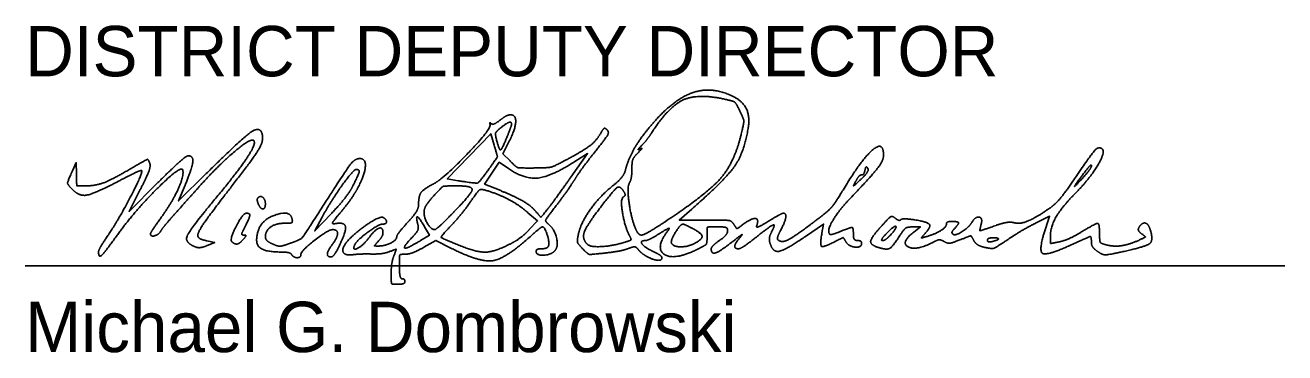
# Model space of a CAD drawing. Extents: x -6.4 to 34, y -1.2 to 22.
# Drawn here: x 25.5 to 29, y 3.231 to 4.142 of the extents above; entities that cross this region are included whole.
import ezdxf

# ---------------------------------------------------------------- set-up
doc = ezdxf.new("R2010")
doc.units = 0
doc.layers.add('GM_X_Airport_Location_Class_3', color=7, linetype='Continuous')
doc.layers.add('GM_X_Township', color=7, linetype='Continuous')

msp = doc.modelspace()

# ---------------------------------------------------------------- linework, layer by layer
at = {"layer": 'GM_X_Airport_Location_Class_3'}
for p, q in [((27.8411, 3.7444), (27.8411, 3.7444)), ((26.1473, 3.6463), (26.1473, 3.6463)), ((26.074, 3.5405), (26.074, 3.5405)), ((25.7038, 3.5122), (25.7038, 3.5122))]:
    msp.add_line(p, q, dxfattribs=at)
for points in [[(26.7032, 3.7097), (26.6728, 3.7146), (26.7937, 3.8403), (26.8032, 3.8082)], [(26.8471, 3.7647), (26.8273, 3.7845), (26.8431, 3.8157)], [(27.0277, 3.7631), (27.0627, 3.7853), (27.016, 3.7193)], [(25.6314, 3.7372), (25.6418, 3.76), (25.6424, 3.7277)], [(26.8166, 3.684), (26.7763, 3.7003), (26.7968, 3.7307), (26.8172, 3.7611), (26.8431, 3.7434)], [(25.9443, 3.6972), (25.9263, 3.6536), (26.0032, 3.7296)], [(25.8197, 3.6852), (25.7885, 3.6245), (25.866, 3.7018)], [(26.3498, 3.6176), (26.3044, 3.57), (26.3252, 3.6087)], [(26.897, 3.6209), (26.9236, 3.598), (26.9008, 3.5738)], [(27.3894, 3.6004), (27.3173, 3.6004), (27.352, 3.6308)], [(28.3075, 3.5916), (28.3462, 3.6108), (28.3348, 3.5761)], [(26.6099, 3.5811), (26.623, 3.5581), (26.5985, 3.5432)], [(27.6683, 3.555), (27.7186, 3.5894), (27.7137, 3.5635)], [(27.9668, 3.5812), (27.9876, 3.5811), (27.9693, 3.567)], [(26.0047, 3.5427), (26.0268, 3.5382), (26.006, 3.5296)], [(26.6073, 3.5246), (26.6406, 3.5436), (26.6864, 3.5207)]]:
    msp.add_lwpolyline(points, dxfattribs=at)
for points in [[(27.467, 3.9441), (27.4102, 3.9725), (27.3049, 3.9384), (27.2472, 3.8728)], [(27.239, 3.8404), (27.2861, 3.914), (27.3666, 3.9528), (27.44, 3.9372)], [(27.44, 3.9372), (27.4676, 3.9313), (27.4755, 3.9254), (27.486, 3.9034)], [(27.5088, 3.855), (27.5142, 3.8878), (27.4942, 3.9305), (27.467, 3.9441)], [(26.8487, 3.893), (26.843, 3.893), (26.8297, 3.8863), (26.8193, 3.8781)], [(26.8431, 3.8157), (26.8614, 3.8515), (26.8644, 3.893), (26.8487, 3.893)], [(27.486, 3.9034), (27.4968, 3.8806), (27.4973, 3.8711), (27.4897, 3.8393)], [(26.0032, 3.7296), (26.0977, 3.8229), (26.1501, 3.8618), (26.157, 3.8437)], [(26.7919, 3.8658), (26.7955, 3.854), (26.6624, 3.7152), (26.6332, 3.7002)], [(26.7948, 3.8686), (26.7918, 3.8716), (26.7905, 3.8703), (26.7919, 3.8658)], [(26.8193, 3.8781), (26.8088, 3.8698), (26.7978, 3.8656), (26.7948, 3.8686)], [(26.8099, 3.8225), (26.8058, 3.8386), (26.8084, 3.8463), (26.8213, 3.8567)], [(26.8213, 3.8567), (26.8372, 3.8696), (26.8514, 3.8743), (26.8514, 3.8666)], [(26.8514, 3.8666), (26.8514, 3.8646), (26.8459, 3.8492), (26.8392, 3.8324)], [(27.0861, 3.7938), (27.114, 3.8286), (27.1229, 3.8449), (27.1171, 3.8507)], [(27.1171, 3.8507), (27.1113, 3.8565), (27.1067, 3.8549), (27.1013, 3.8454)], [(27.2472, 3.8728), (27.2136, 3.8347), (27.1756, 3.7709), (27.168, 3.7398)], [(27.352, 3.6308), (27.4443, 3.7115), (27.4977, 3.7879), (27.5088, 3.855)], [(26.135, 3.8215), (26.1273, 3.8293), (26.0363, 3.7523), (25.9838, 3.6935)], [(26.0419, 3.6764), (26.0961, 3.7418), (26.1425, 3.8141), (26.135, 3.8215)], [(26.157, 3.8437), (26.164, 3.8257), (26.1419, 3.7824), (26.0952, 3.722)], [(26.8392, 3.8324), (26.8249, 3.7966), (26.8171, 3.7939), (26.8099, 3.8225)], [(27.1013, 3.8454), (27.0882, 3.8222), (27.055, 3.7955), (27.0075, 3.77)], [(27.2124, 3.8073), (27.2208, 3.8157), (27.2328, 3.8306), (27.239, 3.8404)], [(27.4897, 3.8393), (27.4708, 3.7606), (27.3943, 3.6726), (27.278, 3.5957)], [(26.8032, 3.8082), (26.8124, 3.7772), (26.8118, 3.7748), (26.7879, 3.7414)], [(27.0278, 3.7145), (27.0383, 3.7313), (27.0646, 3.767), (27.0861, 3.7938)], [(27.1857, 3.7426), (27.1858, 3.7618), (27.1913, 3.7761), (27.2029, 3.7874)], [(27.2029, 3.7874), (27.2123, 3.7966), (27.2149, 3.8013), (27.2086, 3.798)], [(27.2086, 3.798), (27.2024, 3.7947), (27.2041, 3.7989), (27.2124, 3.8073)], [(27.885, 3.7804), (27.885, 3.8217), (27.8234, 3.7686), (27.7724, 3.6835)], [(27.7929, 3.6612), (27.8522, 3.7232), (27.885, 3.7656), (27.885, 3.7804)], [(28.4913, 3.7991), (28.4817, 3.805), (28.4617, 3.7823), (28.4091, 3.7056)], [(28.4203, 3.6773), (28.4591, 3.7165), (28.503, 3.7918), (28.4913, 3.7991)], [(25.6687, 3.6954), (25.6965, 3.6954), (25.7456, 3.715), (25.804, 3.7494)], [(25.804, 3.7494), (25.8369, 3.7688), (25.8417, 3.7699), (25.846, 3.7586)], [(25.846, 3.7586), (25.849, 3.7509), (25.8386, 3.7219), (25.8197, 3.6852)], [(25.866, 3.7018), (25.9086, 3.7442), (25.9477, 3.779), (25.9529, 3.779)], [(25.9529, 3.779), (25.9675, 3.779), (25.9639, 3.7448), (25.9443, 3.6972)], [(26.43, 3.7714), (26.416, 3.7714), (26.3902, 3.7378), (26.3225, 3.6317)], [(26.4251, 3.6915), (26.4438, 3.7271), (26.4466, 3.7714), (26.43, 3.7714)], [(26.8431, 3.7434), (26.8873, 3.7132), (26.9615, 3.7211), (27.0277, 3.7631)], [(26.9143, 3.7451), (26.8733, 3.7448), (26.8644, 3.7474), (26.8471, 3.7647)], [(27.0075, 3.77), (26.9701, 3.7499), (26.9529, 3.7453), (26.9143, 3.7451)], [(27.8411, 3.7444), (27.8381, 3.7491), (27.8349, 3.747), (27.8334, 3.7391)], [(28.4626, 3.7512), (28.4626, 3.7474), (28.452, 3.7324), (28.439, 3.7179)], [(28.4461, 3.7363), (28.4552, 3.7484), (28.4626, 3.7551), (28.4626, 3.7512)], [(25.6329, 3.6838), (25.6178, 3.6989), (25.6176, 3.7071), (25.6314, 3.7372)], [(25.7638, 3.7107), (25.6945, 3.6744), (25.6512, 3.6655), (25.6329, 3.6838)], [(25.6424, 3.7277), (25.643, 3.6962), (25.6437, 3.6954), (25.6687, 3.6954)], [(25.7313, 3.5597), (25.761, 3.6039), (25.8281, 3.7333), (25.8236, 3.7378)], [(25.938, 3.739), (25.9348, 3.7557), (25.8011, 3.6223), (25.7516, 3.553)], [(25.8236, 3.7378), (25.8221, 3.7393), (25.7952, 3.7271), (25.7638, 3.7107)], [(25.8747, 3.6031), (25.9076, 3.6488), (25.9414, 3.7214), (25.938, 3.739)], [(26.0952, 3.722), (26.0175, 3.6217), (25.9771, 3.5634), (25.9798, 3.5553)], [(26.3252, 3.6087), (26.3497, 3.6541), (26.4119, 3.7408), (26.4201, 3.7409)], [(26.4201, 3.7409), (26.4296, 3.7411), (26.4266, 3.7268), (26.4105, 3.6952)], [(26.7879, 3.7414), (26.7619, 3.7052), (26.753, 3.7018), (26.7032, 3.7097)], [(27.016, 3.7193), (26.9903, 3.6829), (26.9619, 3.6439), (26.9529, 3.6325)], [(26.9758, 3.6411), (26.9939, 3.6647), (27.0173, 3.6977), (27.0278, 3.7145)], [(27.168, 3.7398), (27.1653, 3.7286), (27.1492, 3.7086), (27.1323, 3.6952)], [(27.1794, 3.7046), (27.1828, 3.71), (27.1857, 3.7271), (27.1857, 3.7426)], [(27.8081, 3.7088), (27.8005, 3.6947), (27.803, 3.6956), (27.8225, 3.714)], [(27.8239, 3.7258), (27.8202, 3.7258), (27.8131, 3.7182), (27.8081, 3.7088)], [(27.8225, 3.714), (27.8355, 3.7263), (27.8439, 3.7399), (27.8411, 3.7444)], [(27.8334, 3.7391), (27.8319, 3.7318), (27.8277, 3.7258), (27.8239, 3.7258)], [(28.439, 3.7179), (28.4144, 3.6906), (28.4175, 3.6985), (28.4461, 3.7363)], [(25.9838, 3.6935), (25.9531, 3.6592), (25.9178, 3.6196), (25.9052, 3.6056)], [(25.9743, 3.5252), (25.9416, 3.5378), (25.9586, 3.5759), (26.0419, 3.6764)], [(26.4105, 3.6952), (26.4021, 3.6787), (26.3748, 3.6438), (26.3498, 3.6176)], [(26.3786, 3.6246), (26.3954, 3.6447), (26.4163, 3.6748), (26.4251, 3.6915)], [(26.6332, 3.7002), (26.6065, 3.6865), (26.593, 3.6672), (26.593, 3.6425)], [(26.6345, 3.6669), (26.658, 3.6925), (26.6645, 3.6954), (26.6986, 3.6954)], [(26.7413, 3.6876), (26.744, 3.6834), (26.7231, 3.656), (26.6949, 3.6268)], [(26.6986, 3.6954), (26.7195, 3.6954), (26.7387, 3.6919), (26.7413, 3.6876)], [(26.7376, 3.6518), (26.7578, 3.6807), (26.7661, 3.687), (26.7787, 3.6834)], [(26.7787, 3.6834), (26.8144, 3.6729), (26.8721, 3.6425), (26.897, 3.6209)], [(26.9199, 3.6231), (26.9062, 3.6396), (26.8627, 3.6652), (26.8166, 3.684)], [(27.1323, 3.6952), (27.0961, 3.6665), (27.043, 3.5912), (27.0367, 3.5596)], [(27.0927, 3.6279), (27.1354, 3.6838), (27.1527, 3.6968), (27.1628, 3.6804)], [(27.1628, 3.6804), (27.1673, 3.6733), (27.1669, 3.6674), (27.1619, 3.6643)], [(27.1947, 3.5795), (27.1824, 3.611), (27.1723, 3.6935), (27.1794, 3.7046)], [(27.7724, 3.6835), (27.7499, 3.6459), (27.7281, 3.6224), (27.6877, 3.592)], [(28.3486, 3.5554), (28.3486, 3.5824), (28.3812, 3.6377), (28.4203, 3.6773)], [(28.4091, 3.7056), (28.3887, 3.6757), (28.3624, 3.6445), (28.3508, 3.6363)], [(26.1473, 3.6463), (26.1448, 3.6528), (26.1447, 3.66), (26.147, 3.6623)], [(26.147, 3.6623), (26.1536, 3.669), (26.1674, 3.6577), (26.1674, 3.6456)], [(26.1674, 3.6456), (26.1674, 3.631), (26.1529, 3.6315), (26.1473, 3.6463)], [(26.593, 3.6425), (26.593, 3.6338), (26.5794, 3.6118), (26.5626, 3.5937)], [(26.6083, 3.623), (26.6083, 3.6315), (26.6201, 3.6512), (26.6345, 3.6669)], [(26.6853, 3.5871), (26.7002, 3.6028), (26.7237, 3.6319), (26.7376, 3.6518)], [(26.9541, 3.589), (26.9446, 3.5968), (26.9478, 3.6045), (26.9758, 3.6411)], [(27.1619, 3.6643), (27.1535, 3.6591), (27.1659, 3.5822), (27.1791, 3.5571)], [(27.7356, 3.5611), (27.7271, 3.5696), (27.7598, 3.6266), (27.7929, 3.6612)], [(25.9052, 3.6056), (25.8927, 3.5915), (25.8797, 3.5752), (25.8764, 3.5693)], [(26.074, 3.5405), (26.0677, 3.5468), (26.1048, 3.6194), (26.1144, 3.6194)], [(26.1144, 3.6194), (26.125, 3.6194), (26.1236, 3.6069), (26.1102, 3.581)], [(26.2416, 3.6036), (26.2364, 3.6285), (26.1574, 3.602), (26.1479, 3.5722)], [(26.3225, 3.6317), (26.2749, 3.5572), (26.2649, 3.5459), (26.2375, 3.5362)], [(26.3612, 3.5904), (26.352, 3.5887), (26.3573, 3.5991), (26.3786, 3.6246)], [(26.4953, 3.6073), (26.488, 3.6119), (26.4309, 3.5766), (26.4045, 3.5513)], [(26.4931, 3.589), (26.5033, 3.589), (26.5048, 3.6015), (26.4953, 3.6073)], [(26.5909, 3.5886), (26.585, 3.6115), (26.5949, 3.6076), (26.6099, 3.5811)], [(26.6378, 3.5738), (26.6279, 3.5738), (26.6082, 3.6066), (26.6083, 3.623)], [(26.6949, 3.6268), (26.6668, 3.5977), (26.6411, 3.5738), (26.6378, 3.5738)], [(26.9529, 3.6325), (26.934, 3.6085), (26.9324, 3.608), (26.9199, 3.6231)], [(27.0617, 3.5333), (27.0472, 3.5477), (27.059, 3.5837), (27.0927, 3.6279)], [(27.6066, 3.6194), (27.6039, 3.6194), (27.5852, 3.6093), (27.5651, 3.5969)], [(27.5995, 3.5727), (27.6117, 3.5964), (27.6152, 3.6194), (27.6066, 3.6194)], [(27.9177, 3.6054), (27.9095, 3.6123), (27.9017, 3.6081), (27.8809, 3.5854)], [(27.9329, 3.6014), (27.9303, 3.5988), (27.9235, 3.6007), (27.9177, 3.6054)], [(28.1564, 3.589), (28.161, 3.6066), (28.1404, 3.6106), (28.1305, 3.594)], [(28.3508, 3.6363), (28.3099, 3.6075), (28.2652, 3.5887), (28.2479, 3.593)], [(25.8482, 3.5624), (25.8482, 3.5645), (25.8602, 3.5828), (25.8747, 3.6031)], [(26.1102, 3.581), (26.1024, 3.5658), (26.1014, 3.5586), (26.1074, 3.5586)], [(26.1479, 3.5722), (26.1371, 3.538), (26.1643, 3.5115), (26.2102, 3.5115)], [(26.1674, 3.5535), (26.1674, 3.5708), (26.1966, 3.5915), (26.221, 3.5915)], [(26.221, 3.5915), (26.238, 3.5915), (26.2434, 3.5947), (26.2416, 3.6036)], [(26.2662, 3.5048), (26.2662, 3.5146), (26.342, 3.5738), (26.3546, 3.5738)], [(26.3546, 3.5738), (26.3682, 3.5738), (26.3675, 3.5512), (26.3534, 3.5325)], [(26.3744, 3.5323), (26.3927, 3.5699), (26.3869, 3.5951), (26.3612, 3.5904)], [(26.4153, 3.531), (26.4201, 3.5427), (26.4822, 3.589), (26.4931, 3.589)], [(26.4942, 3.5649), (26.4942, 3.5815), (26.472, 3.5739), (26.4555, 3.5516)], [(26.5626, 3.5937), (26.5459, 3.5756), (26.5322, 3.5574), (26.5322, 3.5533)], [(26.5736, 3.5506), (26.5881, 3.5657), (26.5937, 3.578), (26.5909, 3.5886)], [(26.7115, 3.5279), (26.6563, 3.5501), (26.6544, 3.5544), (26.6853, 3.5871)], [(26.9008, 3.5738), (26.8883, 3.5605), (26.865, 3.5429), (26.849, 3.5347)], [(26.9028, 3.5541), (26.9194, 3.5691), (26.9349, 3.5814), (26.9371, 3.5814)], [(26.9371, 3.5814), (26.9438, 3.5814), (26.958, 3.5346), (26.9535, 3.5273)], [(26.9719, 3.5154), (26.9821, 3.5277), (26.9705, 3.5753), (26.9541, 3.589)], [(27.2124, 3.5586), (27.2072, 3.5586), (27.1992, 3.568), (27.1947, 3.5795)], [(27.278, 3.5957), (27.2471, 3.5753), (27.2176, 3.5586), (27.2124, 3.5586)], [(27.2639, 3.5637), (27.2816, 3.5748), (27.2923, 3.5791), (27.2877, 3.5732)], [(27.2877, 3.5732), (27.2489, 3.523), (27.3027, 3.487), (27.3682, 3.5192)], [(27.2961, 3.5356), (27.2922, 3.542), (27.3205, 3.589), (27.3282, 3.589)], [(27.3282, 3.589), (27.3298, 3.589), (27.3411, 3.5838), (27.3534, 3.5774)], [(27.3534, 3.5774), (27.3792, 3.5641), (27.3823, 3.5474), (27.3611, 3.5361)], [(27.4695, 3.5879), (27.4631, 3.5981), (27.4482, 3.6004), (27.3894, 3.6004)], [(27.3948, 3.555), (27.3948, 3.5801), (27.3965, 3.5814), (27.429, 3.5814)], [(27.429, 3.5814), (27.4438, 3.5814), (27.4518, 3.5776), (27.4518, 3.5705)], [(27.4518, 3.5705), (27.4518, 3.5645), (27.4416, 3.5523), (27.429, 3.5434)], [(27.4981, 3.5907), (27.4791, 3.5767), (27.4767, 3.5764), (27.4695, 3.5879)], [(27.5325, 3.5847), (27.5395, 3.603), (27.5194, 3.6065), (27.4981, 3.5907)], [(27.5287, 3.551), (27.5714, 3.5847), (27.5859, 3.5896), (27.5733, 3.5659)], [(27.5651, 3.5969), (27.545, 3.5845), (27.5303, 3.579), (27.5325, 3.5847)], [(27.5915, 3.5456), (27.5893, 3.5478), (27.5929, 3.56), (27.5995, 3.5727)], [(27.6877, 3.592), (27.6367, 3.5537), (27.6008, 3.5363), (27.5915, 3.5456)], [(27.8014, 3.5573), (27.8014, 3.5789), (27.7948, 3.581), (27.7658, 3.5689)], [(27.8809, 3.5854), (27.8513, 3.553), (27.8474, 3.5315), (27.8698, 3.5244)], [(27.8926, 3.5624), (27.9135, 3.5846), (27.9244, 3.5811), (27.9041, 3.5587)], [(27.9288, 3.5548), (27.9416, 3.5747), (27.9512, 3.5814), (27.9668, 3.5812)], [(27.9721, 3.6009), (27.9531, 3.6037), (27.9354, 3.6039), (27.9329, 3.6014)], [(27.9971, 3.5593), (28.0173, 3.5804), (28.0083, 3.5954), (27.9721, 3.6009)], [(28.0598, 3.5899), (28.0598, 3.5813), (28.0311, 3.5625), (28.0066, 3.5551)], [(28.075, 3.5966), (28.0667, 3.5966), (28.0598, 3.5936), (28.0598, 3.5899)], [(28.0812, 3.5755), (28.0945, 3.5887), (28.0922, 3.5966), (28.075, 3.5966)], [(28.0772, 3.5615), (28.0745, 3.5642), (28.0763, 3.5705), (28.0812, 3.5755)], [(28.1305, 3.594), (28.1217, 3.5793), (28.083, 3.5557), (28.0772, 3.5615)], [(28.1976, 3.5855), (28.1548, 3.5705), (28.1517, 3.5707), (28.1564, 3.589)], [(28.2479, 3.593), (28.2385, 3.5954), (28.2159, 3.592), (28.1976, 3.5855)], [(28.2297, 3.5457), (28.2512, 3.5603), (28.2862, 3.581), (28.3075, 3.5916)], [(28.3348, 3.5761), (28.3148, 3.5153), (28.3387, 3.5004), (28.4066, 3.5315)], [(28.4854, 3.5583), (28.4854, 3.5904), (28.4756, 3.5921), (28.4346, 3.5672)], [(28.5538, 3.5133), (28.6153, 3.5269), (28.6354, 3.5442), (28.6257, 3.5749)], [(28.5949, 3.5803), (28.5919, 3.5754), (28.5951, 3.5674), (28.6019, 3.5624)], [(28.6257, 3.5749), (28.6207, 3.5906), (28.6032, 3.5937), (28.5949, 3.5803)], [(25.7038, 3.5122), (25.7038, 3.516), (25.7162, 3.5374), (25.7313, 3.5597)], [(25.7516, 3.553), (25.7204, 3.5092), (25.7038, 3.4951), (25.7038, 3.5122)], [(25.8764, 3.5693), (25.8707, 3.5594), (25.8482, 3.5538), (25.8482, 3.5624)], [(25.9798, 3.5553), (25.9813, 3.5508), (25.9925, 3.5452), (26.0047, 3.5427)], [(26.1066, 3.5472), (26.0968, 3.5354), (26.0822, 3.5324), (26.074, 3.5405)], [(26.1074, 3.5586), (26.1136, 3.5586), (26.1134, 3.5554), (26.1066, 3.5472)], [(26.187, 3.5342), (26.1762, 3.5391), (26.1674, 3.5478), (26.1674, 3.5535)], [(26.2375, 3.5362), (26.213, 3.5276), (26.2024, 3.5271), (26.187, 3.5342)], [(26.4045, 3.5513), (26.3808, 3.5285), (26.3844, 3.5007), (26.4106, 3.5041)], [(26.4555, 3.5516), (26.4393, 3.5298), (26.4083, 3.5138), (26.4153, 3.531)], [(26.4813, 3.5282), (26.4702, 3.5282), (26.4702, 3.5295), (26.4817, 3.5421)], [(26.5322, 3.5533), (26.5322, 3.5446), (26.499, 3.5282), (26.4813, 3.5282)], [(26.4817, 3.5421), (26.4886, 3.5498), (26.4942, 3.56), (26.4942, 3.5649)], [(26.5985, 3.5432), (26.5613, 3.5205), (26.5485, 3.5243), (26.5736, 3.5506)], [(26.6864, 3.5207), (26.764, 3.482), (26.8351, 3.4929), (26.9028, 3.5541)], [(27.0367, 3.5596), (27.0333, 3.5429), (27.0364, 3.5332), (27.0491, 3.5205)], [(27.1574, 3.5362), (27.1253, 3.5273), (27.0694, 3.5256), (27.0617, 3.5333)], [(27.1791, 3.5571), (27.1848, 3.5464), (27.1809, 3.5428), (27.1574, 3.5362)], [(27.245, 3.513), (27.2209, 3.5244), (27.2074, 3.5434), (27.2234, 3.5434)], [(27.2234, 3.5434), (27.228, 3.5434), (27.2462, 3.5525), (27.2639, 3.5637)], [(27.3611, 3.5361), (27.3425, 3.5261), (27.3022, 3.5259), (27.2961, 3.5356)], [(27.3682, 3.5192), (27.3898, 3.5298), (27.3948, 3.5366), (27.3948, 3.555)], [(27.429, 3.5434), (27.4165, 3.5345), (27.4062, 3.524), (27.4062, 3.5201)], [(27.4062, 3.5201), (27.4062, 3.5049), (27.4328, 3.5143), (27.4662, 3.5411)], [(27.4662, 3.5411), (27.4855, 3.5566), (27.4952, 3.5623), (27.4879, 3.5538)], [(27.4879, 3.5538), (27.4731, 3.5367), (27.4705, 3.5206), (27.4825, 3.5206)], [(27.4825, 3.5206), (27.4868, 3.5206), (27.5076, 3.5343), (27.5287, 3.551)], [(27.5733, 3.5659), (27.5687, 3.5574), (27.5671, 3.5437), (27.5697, 3.5355)], [(27.5697, 3.5355), (27.5778, 3.5101), (27.6129, 3.5171), (27.6683, 3.555)], [(27.7137, 3.5635), (27.7076, 3.5307), (27.7179, 3.5239), (27.7492, 3.5401)], [(27.7658, 3.5689), (27.7511, 3.5628), (27.7374, 3.5593), (27.7356, 3.5611)], [(27.7492, 3.5401), (27.7713, 3.5515), (27.7739, 3.5516), (27.7802, 3.5404)], [(27.7802, 3.5404), (27.7876, 3.5272), (27.8242, 3.5234), (27.8242, 3.5358)], [(27.8128, 3.5434), (27.8066, 3.5434), (27.8014, 3.5497), (27.8014, 3.5573)], [(27.8242, 3.5358), (27.8242, 3.54), (27.8191, 3.5434), (27.8128, 3.5434)], [(27.8698, 3.5244), (27.8931, 3.517), (27.91, 3.5257), (27.9288, 3.5548)], [(27.8825, 3.5434), (27.8783, 3.5434), (27.8828, 3.5519), (27.8926, 3.5624)], [(27.9041, 3.5587), (27.8965, 3.5503), (27.8868, 3.5434), (27.8825, 3.5434)], [(27.9693, 3.567), (27.9316, 3.538), (27.9753, 3.5141), (28.0218, 3.5383)], [(28.0066, 3.5551), (27.9911, 3.5503), (27.9894, 3.5511), (27.9971, 3.5593)], [(28.0218, 3.5383), (28.035, 3.5452), (28.0447, 3.5459), (28.0535, 3.5406)], [(28.0535, 3.5406), (28.0624, 3.5352), (28.0752, 3.5366), (28.0972, 3.5452)], [(28.0972, 3.5452), (28.1266, 3.5568), (28.1287, 3.5567), (28.1358, 3.5434)], [(28.1358, 3.5434), (28.1399, 3.5357), (28.1539, 3.5271), (28.1669, 3.5243)], [(28.1669, 3.5243), (28.1862, 3.52), (28.1975, 3.5239), (28.2297, 3.5457)], [(28.1738, 3.5441), (28.1738, 3.5479), (28.1807, 3.551), (28.189, 3.551)], [(28.189, 3.5412), (28.1807, 3.539), (28.1738, 3.5403), (28.1738, 3.5441)], [(28.189, 3.551), (28.1974, 3.551), (28.2042, 3.5497), (28.2042, 3.5481)], [(28.2042, 3.5481), (28.2042, 3.5465), (28.1974, 3.5434), (28.189, 3.5412)], [(28.3733, 3.5398), (28.3502, 3.5349), (28.3486, 3.5359), (28.3486, 3.5554)], [(28.4346, 3.5672), (28.4145, 3.555), (28.3869, 3.5427), (28.3733, 3.5398)], [(28.4066, 3.5315), (28.4567, 3.5544), (28.4626, 3.5552), (28.4626, 3.5385)], [(28.4626, 3.5385), (28.4626, 3.5317), (28.4686, 3.5215), (28.4759, 3.516)], [(28.5045, 3.5313), (28.4896, 3.5351), (28.4854, 3.5409), (28.4854, 3.5583)], [(28.5962, 3.545), (28.5684, 3.5324), (28.5257, 3.526), (28.5045, 3.5313)], [(28.6019, 3.5624), (28.6131, 3.5543), (28.6125, 3.5525), (28.5962, 3.545)], [(26.006, 3.5296), (25.9945, 3.5249), (25.9803, 3.5229), (25.9743, 3.5252)], [(26.2102, 3.5115), (26.2243, 3.5115), (26.2378, 3.5084), (26.2401, 3.5046)], [(26.2401, 3.5046), (26.2456, 3.4957), (26.2662, 3.4958), (26.2662, 3.5048)], [(26.3534, 3.5325), (26.3405, 3.5154), (26.3387, 3.4978), (26.3499, 3.4978)], [(26.3499, 3.4978), (26.3542, 3.4978), (26.3652, 3.5133), (26.3744, 3.5323)], [(26.4106, 3.5041), (26.4211, 3.5055), (26.4439, 3.5063), (26.4614, 3.506)], [(26.4614, 3.506), (26.4788, 3.5056), (26.5018, 3.5086), (26.5124, 3.5127)], [(26.5124, 3.5127), (26.5307, 3.5196), (26.5313, 3.5191), (26.5243, 3.5008)], [(26.5243, 3.5008), (26.5203, 3.4903), (26.517, 3.4682), (26.517, 3.4517)], [(26.5398, 3.4712), (26.5398, 3.5016), (26.5417, 3.5054), (26.5569, 3.5055)], [(26.5569, 3.5055), (26.5663, 3.5056), (26.589, 3.5142), (26.6073, 3.5246)], [(26.849, 3.5347), (26.8058, 3.5125), (26.7559, 3.51), (26.7115, 3.5279)], [(26.9346, 3.5206), (26.9265, 3.5206), (26.9198, 3.5172), (26.9198, 3.513)], [(26.9198, 3.513), (26.9198, 3.5018), (26.9622, 3.5038), (26.9719, 3.5154)], [(26.9535, 3.5273), (26.9512, 3.5236), (26.9427, 3.5206), (26.9346, 3.5206)], [(27.0491, 3.5205), (27.0642, 3.5054), (27.0708, 3.5042), (27.1114, 3.5088)], [(27.1114, 3.5088), (27.1364, 3.5116), (27.1655, 3.5172), (27.1761, 3.5212)], [(27.1761, 3.5212), (27.1904, 3.5267), (27.1975, 3.5258), (27.2039, 3.5179)], [(27.2039, 3.5179), (27.2086, 3.5121), (27.2193, 3.5036), (27.2276, 3.499)], [(27.2693, 3.4959), (27.2692, 3.499), (27.2582, 3.5067), (27.245, 3.513)], [(28.4759, 3.516), (28.4919, 3.5039), (28.5085, 3.5033), (28.5538, 3.5133)], [(26.5474, 3.437), (26.5433, 3.437), (26.5398, 3.4524), (26.5398, 3.4712)], [(27.2276, 3.499), (27.2452, 3.4894), (27.2695, 3.4876), (27.2693, 3.4959)], [(26.517, 3.4517), (26.517, 3.4249), (26.519, 3.4218), (26.536, 3.4218)], [(26.555, 3.4294), (26.555, 3.4336), (26.5516, 3.437), (26.5474, 3.437)], [(26.536, 3.4218), (26.5465, 3.4218), (26.555, 3.4252), (26.555, 3.4294)]]:
    msp.add_open_spline(points, degree=2, dxfattribs=at)
at = {"layer": 'GM_X_Township'}
msp.add_line((25.5, 3.4733), (29, 3.4733), dxfattribs=at)

# ---------------------------------------------------------------- texts
at = {"layer": 'GM_X_Airport_Location_Class_3'}
msp.add_text('Michael G. Dombrowski', height=0.14, dxfattribs=at).set_placement((25.5, 3.2333))
at = {"layer": 'GM_X_Township'}
msp.add_text('DISTRICT DEPUTY DIRECTOR', height=0.14, dxfattribs=at).set_placement((25.5, 4))

doc.saveas('drawing.dxf')
